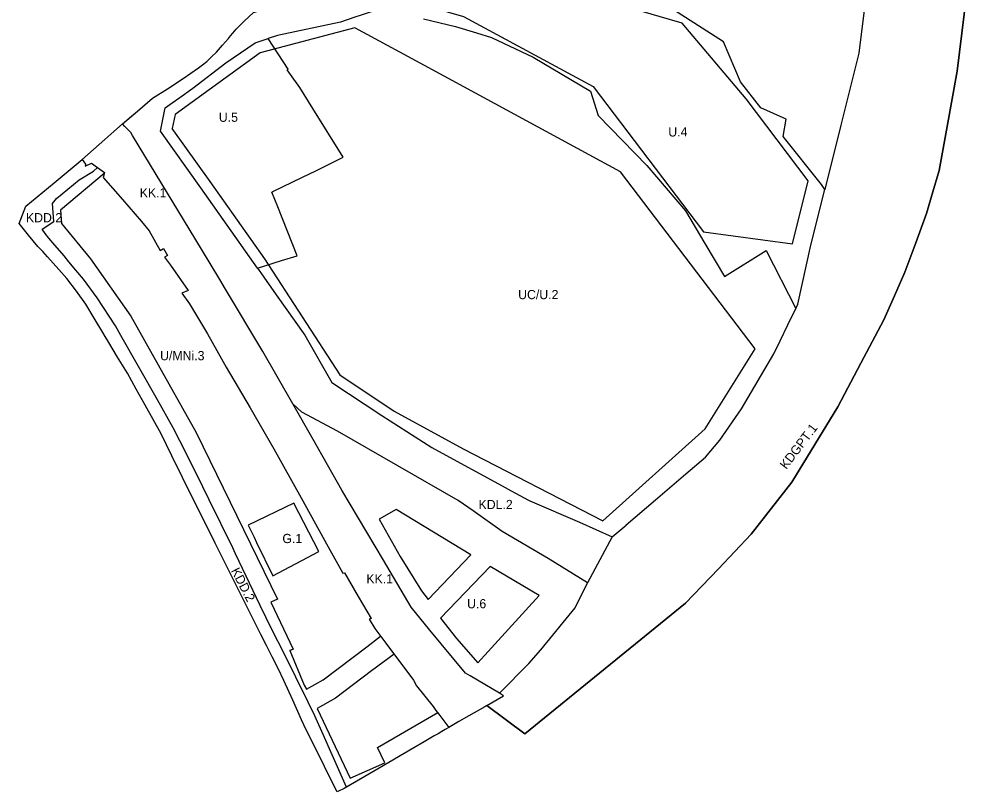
# Model space of a CAD drawing. Extents: x 7427578 to 7429232, y 5547102 to 5548448.
# Drawn here: x 7428107 to 7428624, y 5547102 to 5547522 of the extents above; entities that cross this region are included whole.
import ezdxf

# ---------------------------------------------------------------- set-up
doc = ezdxf.new("R2010")
doc.units = 0
for name, color, linetype in [('LIN_Granica Planu', 7, 'Continuous'), ('LIN_Linia Zabudowy Nieprzekraczalna', 7, 'Continuous'), ('LIN_Linie Rozgraniczajace', 7, 'Continuous'), ('TXT_Oznaczenia Przeznaczenia', 7, 'Continuous')]:
    doc.layers.add(name, color=color, linetype=linetype)

msp = doc.modelspace()

# ---------------------------------------------------------------- linework, layer by layer
at = {"layer": 'LIN_Granica Planu'}
msp.add_lwpolyline([(7428623.59, 5547545.62), (7428617.23, 5547493.78), (7428614.48, 5547478.74), (7428611.73, 5547463.71), (7428609.54, 5547451.71), (7428607.35, 5547439.72), (7428603.92, 5547428.02), (7428600.5, 5547416.32), (7428594.59, 5547400.38), (7428588.68, 5547384.43), (7428582.99, 5547371.49), (7428577.31, 5547358.56), (7428564.71, 5547334.9), (7428552.11, 5547311.25), (7428539.6, 5547290.73), (7428527.08, 5547270.21), (7428516.04, 5547256.04), (7428505.01, 5547241.87), (7428487.17, 5547223.11), (7428469.33, 5547204.35), (7428381.75, 5547133.37), (7428361.23, 5547148.69), (7428360.02, 5547147.98), (7428357.16, 5547146.38), (7428354.29, 5547144.78), (7428351.4, 5547143.16), (7428345.89, 5547139.96), (7428340.38, 5547136.75), (7428338.52, 5547135.67), (7428336.66, 5547134.58), (7428334.6, 5547133.38), (7428332.55, 5547132.19), (7428326.98, 5547128.96), (7428321.41, 5547125.72), (7428302.48, 5547114.68), (7428283.54, 5547103.64), (7428279.68, 5547101.67), (7428276.84, 5547107.42), (7428272.84, 5547115.57), (7428267.82, 5547125.53), (7428262.8, 5547135.49), (7428260.34, 5547140.96), (7428255.53, 5547151.65), (7428250.72, 5547162.34), (7428247.5, 5547168.75), (7428244.28, 5547175.17), (7428241.17, 5547181.29), (7428238.05, 5547187.4), (7428234.62, 5547194.24), (7428231.18, 5547201.08), (7428213.36, 5547236.94), (7428195.54, 5547272.79), (7428189.67, 5547284.6), (7428183.81, 5547296.41), (7428179.47, 5547304.21), (7428175.13, 5547312.01), (7428170.33, 5547320.71), (7428165.52, 5547329.41), (7428160.19, 5547338.26), (7428154.86, 5547347.12), (7428153.46, 5547349.38), (7428152.07, 5547351.65), (7428147.48, 5547359.35), (7428142.89, 5547367.05), (7428137.73, 5547374), (7428132.56, 5547380.95), (7428128.27, 5547385.79), (7428125.17, 5547389.3), (7428122.06, 5547392.81), (7428119.41, 5547395.59), (7428116.75, 5547398.38), (7428111.63, 5547404.59), (7428106.51, 5547410.8), (7428108.41, 5547415.58), (7428110.3, 5547420.37), (7428125.62, 5547433.05), (7428140.94, 5547445.73), (7428153.31, 5547456.64), (7428158.08, 5547460.84), (7428162.84, 5547465.04), (7428171.05, 5547472.06), (7428179.25, 5547479.07), (7428187.34, 5547484.04), (7428195.78, 5547489.77), (7428204.21, 5547495.5), (7428206.45, 5547497.26), (7428208.69, 5547499.03), (7428211.36, 5547501.59), (7428214.02, 5547504.16), (7428217.27, 5547507.84), (7428220.51, 5547511.53), (7428221.67, 5547512.96), (7428222.84, 5547514.39), (7428223.75, 5547515.49), (7428224.65, 5547516.59), (7428226.82, 5547518.77), (7428228.98, 5547520.95), (7428231.59, 5547523.32)], dxfattribs=at)
at = {"layer": 'LIN_Linia Zabudowy Nieprzekraczalna'}
msp.add_lwpolyline([(7428329.45, 5547560.25), (7428317.14, 5547532.66), (7428348.48, 5547523.48), (7428419.09, 5547485.39), (7428479.17, 5547406.37), (7428527.46, 5547399.74), (7428536, 5547434.01), (7428536, 5547434.01), (7428502.3, 5547478.77), (7428467.47, 5547519.82), (7428467.47, 5547519.82), (7428454.97, 5547523.48)], close=True, dxfattribs=at)
for points in [[(7428331.59, 5547494.45), (7428289.32, 5547517.32), (7428289.32, 5547517.32), (7428237.69, 5547503.73), (7428191.5, 5547470.24), (7428189.8, 5547462.56), (7428189.77, 5547462.53), (7428210.42, 5547433.75), (7428240.13, 5547391.64), (7428240.13, 5547391.64)], [(7428507.25, 5547342.65), (7428433.95, 5547439.06), (7428331.63, 5547494.43), (7428331.59, 5547494.45)], [(7428152.82, 5547438.02), (7428129.02, 5547418.19), (7428129.57, 5547410.97), (7428145.36, 5547391.63), (7428167.46, 5547360.49), (7428202.91, 5547297.26), (7428247.15, 5547206.58), (7428247.15, 5547206.58), (7428243.52, 5547204.98), (7428255.74, 5547179.27), (7428253.98, 5547178.58), (7428255.74, 5547179.27), (7428253.98, 5547178.58), (7428261.77, 5547159.76), (7428262.99, 5547157.63), (7428272.14, 5547162.71), (7428295.75, 5547180.61), (7428303.29, 5547186.43)], [(7428240.13, 5547391.64), (7428240.13, 5547391.64)], [(7428240.13, 5547391.64), (7428281.21, 5547328.64), (7428310.67, 5547308.76), (7428348.29, 5547288.35), (7428424.36, 5547249.23)], [(7428424.36, 5547249.23), (7428480.03, 5547299.14), (7428507.25, 5547342.65)], [(7428352.53, 5547230.68), (7428311.74, 5547255.26), (7428302.51, 5547250)], [(7428302.51, 5547250), (7428314.02, 5547229.77), (7428325.5, 5547211.04), (7428329.18, 5547206.35), (7428352.53, 5547230.68)], [(7428363.04, 5547224.34), (7428335.98, 5547196.28), (7428344.59, 5547185.18), (7428356.25, 5547171.86)], [(7428356.25, 5547171.86), (7428389.65, 5547208.56), (7428363.04, 5547224.34)], [(7428310.7, 5547176.62), (7428298.29, 5547167.65), (7428278.76, 5547152.65), (7428268.81, 5547147.13), (7428286.73, 5547109.1), (7428305.57, 5547117.53), (7428301.72, 5547125.8), (7428334.39, 5547144.83)]]:
    msp.add_lwpolyline(points, dxfattribs=at)
at = {"layer": 'LIN_Linie Rozgraniczajace'}
msp.add_line((7428429.42, 5547240.4), (7428415.89, 5547215.39), dxfattribs=at)
for points in [[(7428545.16, 5547429.45), (7428543.24, 5547432.02), (7428522.47, 5547458.21), (7428524.09, 5547467.7), (7428510.35, 5547473.76), (7428499.26, 5547487.9), (7428490.03, 5547509.61), (7428460.3, 5547528.82), (7428439.33, 5547543.71), (7428424.82, 5547554), (7428418.3, 5547558.63), (7428383.69, 5547582.11), (7428341.88, 5547597.87)], [(7428361.23, 5547148.69), (7428381.75, 5547133.37), (7428469.33, 5547204.35), (7428487.17, 5547223.11), (7428505.01, 5547241.87), (7428516.04, 5547256.04), (7428527.08, 5547270.21), (7428539.6, 5547290.73), (7428552.11, 5547311.25), (7428564.71, 5547334.9), (7428577.31, 5547358.56), (7428582.99, 5547371.49), (7428588.68, 5547384.43), (7428594.59, 5547400.38), (7428600.5, 5547416.32), (7428603.92, 5547428.02), (7428607.35, 5547439.72), (7428609.54, 5547451.71), (7428611.73, 5547463.71), (7428614.48, 5547478.74), (7428617.23, 5547493.78), (7428623.59, 5547545.62)], [(7428162.84, 5547465.04), (7428166.65, 5547468.39), (7428171.05, 5547472.06), (7428179.25, 5547479.07), (7428187.34, 5547484.04), (7428195.78, 5547489.77), (7428204.21, 5547495.5), (7428206.45, 5547497.26), (7428208.69, 5547499.03), (7428211.36, 5547501.59), (7428214.02, 5547504.16), (7428217.27, 5547507.84), (7428220.51, 5547511.53), (7428221.67, 5547512.96), (7428222.84, 5547514.39), (7428223.75, 5547515.49), (7428224.65, 5547516.59), (7428226.82, 5547518.77), (7428228.98, 5547520.95), (7428231.59, 5547523.32), (7428234.21, 5547525.69), (7428242.1, 5547527.99)], [(7428312.16, 5547530.77), (7428292.78, 5547524.27), (7428289.37, 5547523.1), (7428281.59, 5547520.42), (7428247.17, 5547513.22), (7428242.05, 5547511.49)], [(7428326.59, 5547522.29), (7428344.08, 5547518.11), (7428355.51, 5547514.59), (7428363.67, 5547512.1), (7428363.67, 5547512.1), (7428363.67, 5547512.1), (7428386.31, 5547501.37), (7428386.31, 5547501.37), (7428386.31, 5547501.37), (7428417.66, 5547482.91), (7428421.68, 5547469.71), (7428448.18, 5547442.43), (7428469.33, 5547417.72), (7428479.85, 5547400.06), (7428479.85, 5547400.06), (7428479.85, 5547400.06), (7428490.52, 5547382.13), (7428490.52, 5547382.13), (7428490.52, 5547382.13), (7428490.52, 5547382.13), (7428513.26, 5547396.24), (7428529.26, 5547364.65)], [(7428566.6, 5547526.89), (7428563.7, 5547503.51), (7428553.9, 5547464.36), (7428545.16, 5547429.45)], [(7428236.3, 5547386.65), (7428205.53, 5547430.28), (7428183.49, 5547461.13), (7428186.11, 5547473.8), (7428189.9, 5547476.44), (7428194.01, 5547479.33), (7428201.18, 5547484.51), (7428219.04, 5547498.29), (7428219.12, 5547498.34), (7428235.01, 5547509.16), (7428242.05, 5547511.49)], [(7428236.3, 5547386.65), (7428249.46, 5547390.71), (7428257.83, 5547393.29), (7428247.33, 5547419.98), (7428244.18, 5547427.98), (7428244.71, 5547428.26), (7428260.74, 5547436), (7428268.05, 5547439.53), (7428282.88, 5547447.01), (7428266.53, 5547473.44), (7428259.44, 5547484.88), (7428254.32, 5547491.86), (7428252.48, 5547494.39), (7428253.05, 5547494.76), (7428242.05, 5547511.49)], [(7428140.94, 5547445.73), (7428153.31, 5547456.64), (7428158.08, 5547460.84), (7428162.84, 5547465.04)], [(7428255.57, 5547312.78), (7428239.23, 5547341.3), (7428218.99, 5547375.22), (7428215.87, 5547380.36), (7428210.55, 5547389.13), (7428202.74, 5547402.03), (7428168.31, 5547458.74), (7428167.34, 5547460.35), (7428164.16, 5547463.66), (7428162.84, 5547465.04)], [(7428284.7, 5547104.31), (7428283.54, 5547103.64), (7428279.68, 5547101.67), (7428276.84, 5547107.42), (7428272.84, 5547115.57), (7428267.82, 5547125.53), (7428262.8, 5547135.49), (7428260.34, 5547140.96), (7428255.53, 5547151.65), (7428250.72, 5547162.34), (7428247.5, 5547168.75), (7428244.28, 5547175.17), (7428241.17, 5547181.29), (7428238.05, 5547187.4), (7428234.62, 5547194.24), (7428231.18, 5547201.08), (7428213.36, 5547236.94), (7428195.54, 5547272.79), (7428189.67, 5547284.6), (7428183.81, 5547296.41), (7428179.47, 5547304.21), (7428175.13, 5547312.01), (7428170.33, 5547320.71), (7428165.52, 5547329.41), (7428160.19, 5547338.26), (7428154.86, 5547347.12), (7428153.46, 5547349.38), (7428152.07, 5547351.65), (7428147.48, 5547359.35), (7428142.89, 5547367.05), (7428137.73, 5547374), (7428132.56, 5547380.95), (7428128.27, 5547385.79), (7428125.17, 5547389.3), (7428122.06, 5547392.81), (7428119.41, 5547395.59), (7428116.75, 5547398.38), (7428111.63, 5547404.59), (7428106.51, 5547410.8), (7428108.41, 5547415.58), (7428110.3, 5547420.37), (7428125.62, 5547433.05), (7428140.94, 5547445.73)], [(7428140.94, 5547445.73), (7428142.72, 5547443.11), (7428142.49, 5547442.12), (7428146.03, 5547443.74), (7428149.24, 5547441.32)], [(7428284.7, 5547104.31), (7428271.35, 5547134.65), (7428268.95, 5547139.9), (7428267.46, 5547143.16), (7428263.92, 5547150.48), (7428257.19, 5547164.15), (7428250.72, 5547177.29), (7428244.36, 5547189.77), (7428237.76, 5547203.05), (7428224.41, 5547231.29), (7428222.88, 5547234.51), (7428210.08, 5547260.53), (7428203.09, 5547274.76), (7428194.04, 5547292.62), (7428190.45, 5547299.71), (7428181.87, 5547314.99), (7428161.95, 5547349.94), (7428159, 5547355.13), (7428149.04, 5547370.37), (7428141.65, 5547380.61), (7428137.4, 5547385.56), (7428133.62, 5547390.11), (7428131.01, 5547393.24), (7428124.98, 5547400.29), (7428122.79, 5547402.83), (7428120.84, 5547405.53), (7428119.15, 5547407.88), (7428125.48, 5547411.96), (7428124.73, 5547421.79), (7428127.01, 5547424.44), (7428139.25, 5547434.68), (7428146.99, 5547439.33), (7428149.24, 5547441.32)], [(7428149.24, 5547441.32), (7428152.96, 5547438.57), (7428152.27, 5547435.9), (7428162.77, 5547423.89), (7428173.27, 5547411.88), (7428177.44, 5547406.84), (7428183.37, 5547396.24), (7428185.1, 5547397.34), (7428187.4, 5547393.51), (7428185.79, 5547392.66), (7428188.89, 5547388.25), (7428198.64, 5547374.42), (7428195.23, 5547372.92), (7428199.4, 5547367.11), (7428209.18, 5547350.9), (7428219.33, 5547332.8), (7428232.31, 5547310.57), (7428245.29, 5547288.33), (7428260.03, 5547261.7), (7428274.78, 5547235.08), (7428282.78, 5547220.63), (7428283.61, 5547220.94), (7428291.17, 5547207.91), (7428298.19, 5547196), (7428297.17, 5547195.62), (7428300.16, 5547190.56), (7428306.14, 5547182.66), (7428321.32, 5547162.57), (7428322.84, 5547159.42), (7428327.37, 5547153.76), (7428331.9, 5547148.11), (7428333.44, 5547146.05), (7428334.97, 5547143.99), (7428337.67, 5547140.37), (7428340.38, 5547136.75)], [(7428529.26, 5547364.65), (7428530.42, 5547367.07), (7428537.58, 5547399.17), (7428545.16, 5547429.45)], [(7428236.3, 5547386.65), (7428239.38, 5547382.29), (7428239.74, 5547381.78), (7428246.56, 5547372.11), (7428262.09, 5547350.09), (7428276.71, 5547324.42), (7428304.02, 5547306.48), (7428331.28, 5547289.05), (7428336.77, 5547286.05), (7428369.44, 5547268.21), (7428374.43, 5547265.49), (7428383.74, 5547260.4), (7428384.5, 5547259.99), (7428411.57, 5547248.36), (7428429.42, 5547240.4)], [(7428429.42, 5547240.4), (7428436.95, 5547246.85), (7428437.05, 5547246.94), (7428452.92, 5547260.53), (7428469.43, 5547274.68), (7428480.13, 5547283.85), (7428487.96, 5547293.02), (7428499.85, 5547310.1), (7428517.36, 5547339.98), (7428520.81, 5547347.14), (7428524.97, 5547355.75), (7428529.26, 5547364.65)], [(7428368.02, 5547155.37), (7428352.07, 5547164.88), (7428349.48, 5547166.25), (7428330.21, 5547189.66), (7428319.93, 5547202.17), (7428304.96, 5547227.82), (7428282.25, 5547265.9), (7428266.7, 5547293.35), (7428255.57, 5547312.78)], [(7428415.89, 5547215.39), (7428394.57, 5547228.58), (7428369.57, 5547243.32), (7428353.75, 5547254.64), (7428345.46, 5547260.26), (7428279.81, 5547297.96), (7428260.4, 5547308.19), (7428255.57, 5547312.78)], [(7428231.23, 5547246.72), (7428234.49, 5547240.22), (7428235.8, 5547237.4), (7428244.72, 5547219.32), (7428269.69, 5547232.41), (7428256.09, 5547258.73), (7428231.23, 5547246.72)], [(7428368.02, 5547155.37), (7428384.1, 5547171.53), (7428390.55, 5547179.03), (7428409.29, 5547201.84), (7428415.89, 5547215.39)], [(7428361.23, 5547148.69), (7428370.3, 5547154.01), (7428368.02, 5547155.37)], [(7428361.23, 5547148.69), (7428360.02, 5547147.98), (7428357.16, 5547146.38), (7428354.29, 5547144.78), (7428351.4, 5547143.16), (7428345.89, 5547139.96), (7428340.38, 5547136.75)], [(7428340.38, 5547136.75), (7428338.52, 5547135.67), (7428336.66, 5547134.58), (7428334.6, 5547133.38), (7428332.55, 5547132.19), (7428326.98, 5547128.96), (7428321.41, 5547125.72), (7428302.48, 5547114.68), (7428284.7, 5547104.31)]]:
    msp.add_lwpolyline(points, dxfattribs=at)

# ---------------------------------------------------------------- texts
at = {"layer": 'TXT_Oznaczenia Przeznaczenia'}
for s, p in [('U.5', (7428215.28, 5547466.19)), ('U.4', (7428459.92, 5547458.21)), ('KK.1', (7428172.25, 5547425.1)), ('KDD.2', (7428110.3, 5547411.54)), ('UC/U.2', (7428378.2, 5547369.73)), ('U/MNi.3', (7428183.31, 5547336.51)), ('KDL.2', (7428356.65, 5547255.53)), ('G.1', (7428249.87, 5547237.05)), ('KK.1', (7428295.58, 5547215.13)), ('U.6', (7428350.4, 5547201.59))]:
    msp.add_text(s, height=5, dxfattribs=at).set_placement(p)
for s, rotation, p in [('KDGPT.1', 52.7868, (7428524.18, 5547276.82)), ('KDD.2', 297.498, (7428221.76, 5547222.06))]:
    msp.add_text(s, height=5, rotation=rotation, dxfattribs=at).set_placement(p)

doc.saveas('drawing.dxf')
